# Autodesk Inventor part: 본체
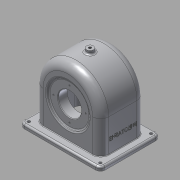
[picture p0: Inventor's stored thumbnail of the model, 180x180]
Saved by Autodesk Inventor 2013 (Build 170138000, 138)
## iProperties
Created: 2016-01
Part Number: 본체
Material: 알루미늄 6061
Document SubType Name: Modeling
Designer: dgall
Mass: 809.57 g
Surface Area: 999.65 cm^2
Volume: 298.734 cm^3
Density: 2.71 g/cm^3
Author: dgall
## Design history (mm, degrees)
sketch "스케치1"
  geometry: L1 (0, 0)-(140, 0); L2 (140, 0)-(140, 104); L3 (140, 104)-(0, 104); L4 (0, 104)-(0, 0); 1 further point
  constraints: 8 end point, 2 parallel, 1 coincident, 1 horizontal, 1 perpendicular
  dimensions: "d0" = 140 distance of L2.end L3.end; "d2" = 104 distance of L1.end L2.end
extrude "돌출1" new body sketch "스케치1" distance "d3" = 7; taper "d4" = 0 deg
sketch "스케치2"
  geometry: L1 (0, 0)-(140, 0) reference; L2 (140, 0)-(140, 104) reference; L3 (140, 104)-(0, 104) reference; L4 (0, 104)-(0, 0) reference; L5 (13, 90.5)-(127, 90.5); L6 (127, 90.5)-(127, 13.5); L7 (127, 13.5)-(13, 13.5); L8 (13, 13.5)-(13, 90.5); L9 (70, 104)-(70, 0); L10 (0, 52)-(140, 52); 2 further points
  constraints: 12 end point, 6 midpoint, 2 parallel, 2 point on line, 1 horizontal, 1 perpendicular
  dimensions: "d5" = 114 distance of L5.start L5.end; "d7" = 77 distance of L7.end L5.start
extrude "돌출2" join sketch "스케치2" distance "d8" = 114; taper "d9" = 0 deg
fillet "모깎기1" dims "d10" = 57
node "작업 평면1"
sketch "스케치3"
  geometry: L1 (127, 0)-(127, -7) reference; L2 (127, -7)-(-13, -7) reference; L3 (-13, -7)-(-13, 0) reference; L4 (-13, 0)-(0, 0) reference; L5 (0, 0)-(0, 57) reference; L6 (114, 57)-(114, 0) reference; L7 (114, 0)-(127, 0) reference; L8 (6, -7)-(6, 57); L9 (108, 57)-(108, -7); L10 (6, -7)-(108, -7); A1 r 57 centre (57, 57) between (114, 57) and (0, 57) reference; A2 r 51 centre (57, 57) between (108, 57) and (6, 57)
  constraints: 6 end point, 2 perpendicular, 2 point on circle, 2 point on line, 2 tangent, 1 centre point, 1 coincident
  dimensions: "d12" = 6 radial gap between concentric circles of A1 A2
extrude "돌출3" cut sketch "스케치3" distance "d13" = 67; taper "d14" = 0 deg
fillet "모깎기2" dims "d15" = 9
fillet "모깎기3" dims "d16" = 14
fillet "모깎기4" dims "d17" = 8
fillet "모깎기5" dims "d18" = 3
node "작업 평면2"
sketch "스케치4"
  geometry: L1 (-108, 49)-(-108, 0) reference; L2 (-99, -9)-(7, -9) reference; L3 (7, -9)-(7, -27.5) reference; L4 (7, -27.5)-(3, -27.5) reference; L5 (0, -24.5)-(0, -14) reference; L6 (0, -14)-(-100, -14) reference; L7 (-114, 0)-(-114, 49) reference; L8 (-100, 63)-(0, 63) reference; L9 (0, 63)-(0, 73.5) reference; L10 (3, 76.5)-(7, 76.5) reference; L11 (7, 76.5)-(7, 58) reference; L12 (7, 58)-(-99, 58) reference; L13 (-53, -14)-(-53, 63); L14 (-90.416, -14)-(-90.416, -9); L15 (-53, -9)-(-90.416, -9); L16 (-90.416, -14)-(-53, -14); A1 r 9 centre (-99, 49) between (-99, 58) and (-108, 49) reference; A2 r 9 centre (-99, 0) between (-108, 0) and (-99, -9) reference; A3 r 3 centre (3, -24.5) between (0, -24.5) and (3, -27.5) reference; A4 r 14 centre (-100, 0) between (-114, 0) and (-100, -14) reference; A5 r 14 centre (-100, 49) between (-100, 63) and (-114, 49) reference; A6 r 3 centre (3, 73.5) between (3, 76.5) and (0, 73.5) reference
  constraints: 8 end point, 6 point on line, 2 perpendicular, 1 collinear
  dimensions: "d19" = 60 distance between parallel lines of L11 L13
revolve "회전1" sketch "스케치4" stored, may be unused: angle "d24" = 90 deg
sketch "스케치5"
  geometry: L1 (7, -9)-(7, -27.5) reference; L2 (7, -27.5)-(3, -27.5) reference; L3 (0, -24.5)-(0, -14) reference; L4 (0, -14)-(-15.584, -14) reference; L5 (-15.584, -14)-(-15.584, -9) reference; L6 (-15.584, -9)-(7, -9) reference; L7 (-108, 49)-(-108, 0) reference; L8 (-99, -9)-(-90.416, -9) reference; L9 (-90.416, -9)-(-90.416, -14) reference; L10 (-90.416, -14)-(-100, -14) reference; L11 (-114, 0)-(-114, 49) reference; L12 (-100, 63)-(0, 63) reference; L13 (0, 63)-(0, 73.5) reference; L14 (3, 76.5)-(7, 76.5) reference; L15 (7, 76.5)-(7, 58) reference; L16 (7, 58)-(-99, 58) reference; L17 (-53, 63)-(-53, -14); L18 (-73, 5)-(-81, 5); L19 (-81, 5)-(-92.747, -9); L20 (-90.416, -14)-(-87.899, -11); L21 (-87.899, -11)-(-73, -11); L22 (-73, -11)-(-73, 5); A1 r 3 centre (3, -24.5) between (0, -24.5) and (3, -27.5) reference; A2 r 9 centre (-99, 49) between (-99, 58) and (-108, 49) reference; A3 r 9 centre (-99, 0) between (-108, 0) and (-99, -9) reference; A4 r 14 centre (-100, 0) between (-114, 0) and (-100, -14) reference; A5 r 14 centre (-100, 49) between (-100, 63) and (-114, 49) reference; A6 r 3 centre (3, 73.5) between (3, 76.5) and (0, 73.5) reference
  constraints: 12 end point, 3 perpendicular, 2 parallel, 2 point on line
  dimensions: "d25" = 60 distance between parallel lines of L15 L17; "d26" = 56 diameter of L18.end L17; "d28" = 50 deg angle of L18 L19; "d29" = 5 distance between parallel lines of L19 L20; "d30" = 3 distance between parallel lines of L10 L21; "d31" = 40 diameter of L22 L17
revolve "회전2" sketch "스케치5" stored, may be unused: angle "d32" = 90 deg
sketch "스케치6"
  geometry: L1 (85, 7)-(1, 7) reference; C1 r 31 at (43, -53); 1 further point
  constraints: 1 centre point
  dimensions: "d33" = 60 distance from line of L1 C1.centre; "d34" = 62 diameter of C1
extrude "돌출4" join sketch "스케치6" distance "d35" = 10; taper "d36" = 0 deg
sketch "스케치7"
  geometry: C1 r 31 at (0, 0) reference; C2 r 20 at (0, 0); 1 further point
  constraints: 1 centre point, 1 coincident
  dimensions: "d37" = 40 diameter of C2
extrude "돌출5" cut sketch "스케치7" stored distance "d39" = 10; taper "d40" = 0 deg
fillet "모깎기6" dims "d41" = 1
fillet "모깎기7" dims "d42" = 3
chamfer "모따기1" distance "d43" = 1; stored, may be unused: second distance "d44" = 2, angle "d45" = 45 deg
node "작업 평면3"
sketch "스케치8"
  geometry: L1 (13, 76.5)-(127, 76.5) reference; L2 (13, 76.5)-(13, 27.5) reference; L3 (127, 27.5)-(13, 27.5) reference; L4 (127, 27.5)-(127, 76.5) reference; L5 (28, 18.5)-(112, 18.5) reference; C1 r 6 at (70, 52); 2 further points
  constraints: 1 centre point, 1 midpoint, 1 vertical alignment
  dimensions: "d47" = 12 diameter of C1; "d49" = 33.5 distance from line of C1.centre L5
extrude "돌출6" join sketch "스케치8" stored distance "d50" = 10; taper "d51" = 0 deg
fillet "모깎기8" dims "d52" = 3
sketch "스케치9"
  geometry: C1 r 6 at (0, 0) reference; 1 further point
hole "구멍1" sketch "스케치9" at (0, 0) diameter "d53" = 4.459; stored, may be unused: countersink angle "d57" = 90 deg, drill point angle "d59" = 118 deg; dims "d54" = 6, "d55" = 4, "d56" = 2, "d58" = 8
sketch "스케치10" dims "d60" = 56
  geometry: C1 r 33.5 at (0, 0) reference; C2 r 21 at (0, 0) reference; 6 further points
  constraints: 2 vertical alignment, 1 coincident, 7 other
  dimensions: "d64" = 360 deg dimension on C1.centre point (0, 28) (derived)
hole "구멍2" sketch "스케치10" at (0, 28), (-28, 0), (0, -28), (28, 0) diameter "d66" = 2.459; stored, may be unused: countersink angle "d70" = 90 deg, drill point angle "d72" = 118 deg; dims "d67" = 7, "d68" = 4, "d69" = 2, "d71" = 9
sketch "스케치11" dims "d73" = 48
  geometry: C1 r 20 at (0, 0) reference; C2 r 31 at (0, 0) reference; 6 further points
  constraints: 2 vertical alignment, 1 coincident, 7 other
  dimensions: "d77" = 360 deg dimension on C1.centre point (0, -24) (derived)
hole "구멍3" sketch "스케치11" at (0, -24), (24, 0), (0, 24), (-24, 0) diameter "d79" = 2.459; stored, may be unused: countersink angle "d83" = 90 deg, drill point angle "d85" = 118 deg; dims "d80" = 6, "d81" = 4, "d82" = 2, "d84" = 8
fillet "모깎기9" dims "d86" = 3
chamfer "모따기2" distance "d87" = 1; stored, may be unused: second distance "d88" = 2, angle "d89" = 45 deg
sketch "스케치12"
  geometry: L1 (26.752, -0.387)-(26.752, 49.387); L2 (26.752, 49.387)-(41.248, 49.387); L3 (41.248, 49.387)-(41.248, -0.387); L4 (41.248, -0.387)-(26.752, -0.387); L5 (34, -0.387)-(34, 49.387); L6 (26.752, 24.5)-(41.248, 24.5); L7 (0, -14)-(56, -14) reference; L8 (64, -19.5)-(64, 68.5) reference; 1 further point
  constraints: 4 end point, 4 midpoint, 2 other
  dimensions: "d90" = 38.5 distance between parallel lines of L6 L7; "d91" = 30 distance between parallel lines of L8 L5
extrude "돌출7" join sketch "스케치12" distance "d92" = 0.5; taper "d93" = 0 deg
sketch "스케치13"
  geometry: C1 r 2.5 at (8, 96); C2 r 2.5 at (8, 8); C3 r 2.5 at (132, 8); C4 r 2.5 at (132, 96); A1 r 5 centre (132, 8) between (132, 3) and (137, 8) reference; A2 r 5 centre (132, 96) between (137, 96) and (132, 101) reference; A3 r 5 centre (8, 96) between (8, 101) and (3, 96) reference; A4 r 5 centre (8, 8) between (3, 8) and (8, 3) reference; 1 further point
  constraints: 4 centre point, 4 coincident, 3 equal radius
  dimensions: "d94" = 5 diameter of C1
extrude "돌출8" cut sketch "스케치13" stored distance "d97" = 0.5; taper "d98" = 0 deg
node "솔리드1"
node "투영된 루프1"
node "절단 모서리 투영1"
node "절단 모서리 투영2"
node "절단 모서리 투영3"
other parameters: "d11" = -5, "d46" = -127
